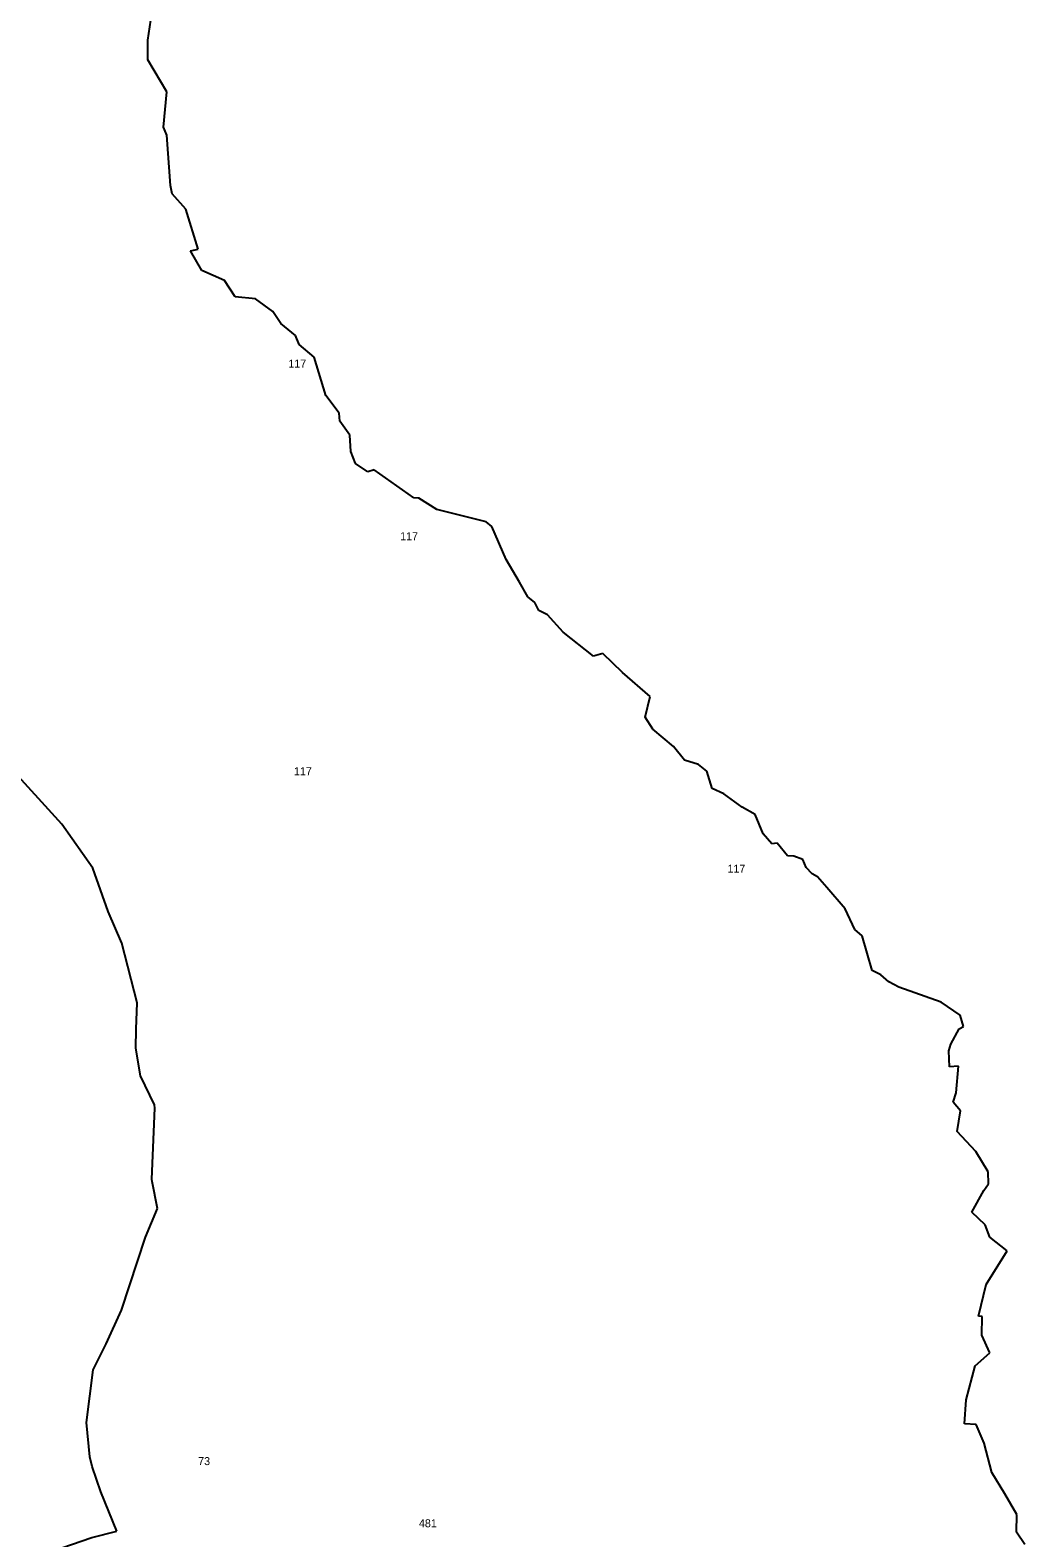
# Model space of a CAD drawing. Extents: x -782977 to -778030, y -975420 to -964838.
# Drawn here: x -780704 to -779844, y -972772 to -971468 of the extents above; entities that cross this region are included whole.
import ezdxf

# ---------------------------------------------------------------- set-up
doc = ezdxf.new("R2010")
doc.units = 0
doc.layers.add('Vrstva 13', color=7, linetype='Continuous')
doc.layers.add('Vrstva 24', color=7, linetype='Continuous')

msp = doc.modelspace()

# ---------------------------------------------------------------- linework, layer by layer
at = {"layer": 'Vrstva 13'}
for p, q in [((-780602.17, -971477.03), (-780599.62, -971459.93)), ((-780602.06, -971494.12), (-780602.17, -971477.03)), ((-780585.78, -971521.81), (-780602.06, -971494.12)), ((-780588.63, -971552.35), (-780585.78, -971521.81)), ((-780585.58, -971559.27), (-780588.63, -971552.35)), ((-780582.42, -971602.63), (-780585.58, -971559.27)), ((-780581.07, -971610.08), (-780582.42, -971602.63)), ((-780569.27, -971623.06), (-780581.07, -971610.08)), ((-780558.65, -971657.66), (-780569.27, -971623.06)), ((-780565.16, -971659.24), (-780558.65, -971657.66)), ((-780555.34, -971676.3), (-780565.16, -971659.24)), ((-780535.9, -971684.96), (-780555.34, -971676.3)), ((-780526.54, -971698.9), (-780535.9, -971684.96)), ((-780509.09, -971700.78), (-780526.54, -971698.9)), ((-780494.08, -971711.62), (-780509.09, -971700.78)), ((-780487.06, -971721.9), (-780494.08, -971711.62)), ((-780474.49, -971732.43), (-780487.06, -971721.9)), ((-780471.19, -971740.17), (-780474.49, -971732.43)), ((-780458.35, -971750.99), (-780471.19, -971740.17)), ((-780448.3, -971784.25), (-780458.35, -971750.99)), ((-780436.7, -971799.47), (-780448.3, -971784.25)), ((-780436.03, -971806.29), (-780436.7, -971799.47)), ((-780427.59, -971818.5), (-780436.03, -971806.29)), ((-780426.48, -971832.65), (-780427.59, -971818.5)), ((-780422.51, -971843.09), (-780426.48, -971832.65)), ((-780411.85, -971850.24), (-780422.51, -971843.09)), ((-780406.46, -971848.61), (-780411.85, -971850.24)), ((-780372.25, -971872.55), (-780406.46, -971848.61)), ((-780367.72, -971872.86), (-780372.25, -971872.55)), ((-780352.28, -971882.86), (-780367.72, -971872.86)), ((-780309.57, -971893.32), (-780352.28, -971882.86)), ((-780304.61, -971897.57), (-780309.57, -971893.32)), ((-780292.4, -971925.87), (-780304.61, -971897.57)), ((-780280.74, -971945.5), (-780292.4, -971925.87)), ((-780273.56, -971958.17), (-780280.74, -971945.5)), ((-780267.55, -971963.19), (-780273.56, -971958.17)), ((-780264.01, -971970.09), (-780267.55, -971963.19)), ((-780256.62, -971973.74), (-780264.01, -971970.09)), ((-780242.98, -971988.81), (-780256.62, -971973.74)), ((-780216.85, -972009.55), (-780242.98, -971988.81)), ((-780208.66, -972007.29), (-780216.85, -972009.55)), ((-780191.71, -972023.77), (-780208.66, -972007.29)), ((-780167.8, -972044.23), (-780191.71, -972023.77)), ((-780172.08, -972062.14), (-780167.8, -972044.23)), ((-780165.57, -972072.53), (-780172.08, -972062.14)), ((-780147.66, -972087.59), (-780165.57, -972072.53)), ((-780138.2, -972099.29), (-780147.66, -972087.59)), ((-780125.99, -972103.16), (-780138.2, -972099.29)), ((-780676.27, -972154.73), (-780722.73, -972103.79)), ((-780118.95, -972108.98), (-780125.99, -972103.16)), ((-780114.32, -972123.89), (-780118.95, -972108.98)), ((-780104.15, -972128.57), (-780114.32, -972123.89)), ((-780088.43, -972139.92), (-780104.15, -972128.57)), ((-780077.04, -972146.29), (-780088.43, -972139.92)), ((-780070.27, -972162.98), (-780077.04, -972146.29)), ((-780649.54, -972192.64), (-780676.27, -972154.73)), ((-780062.68, -972171.84), (-780070.27, -972162.98)), ((-780058, -972171.16), (-780062.68, -972171.84)), ((-780049.08, -972181.98), (-780058, -972171.16)), ((-780043.79, -972182.23), (-780049.08, -972181.98)), ((-780035.8, -972185.34), (-780043.79, -972182.23)), ((-780033.16, -972192.11), (-780035.8, -972185.34)), ((-780636.22, -972230.05), (-780649.54, -972192.64)), ((-780027.82, -972197.7), (-780033.16, -972192.11)), ((-780023.34, -972200.35), (-780027.82, -972197.7)), ((-780015.25, -972209.36), (-780023.34, -972200.35)), ((-779999.23, -972227.93), (-780015.25, -972209.36)), ((-779990.89, -972245.68), (-779999.23, -972227.93)), ((-780624.55, -972257.62), (-780636.22, -972230.05)), ((-779984.63, -972251.28), (-779990.89, -972245.68)), ((-779975.88, -972281.15), (-779984.63, -972251.28)), ((-780611.35, -972309.17), (-780624.55, -972257.62)), ((-779968.46, -972284.96), (-779975.88, -972281.15)), ((-779961.44, -972290.87), (-779968.46, -972284.96)), ((-779953.05, -972295.66), (-779961.44, -972290.87)), ((-779916.19, -972308.66), (-779953.05, -972295.66)), ((-780612.19, -972331.79), (-780611.35, -972309.17)), ((-779899.82, -972319.79), (-779916.19, -972308.66)), ((-779897.06, -972329.49), (-779899.82, -972319.79)), ((-780612.59, -972348.4), (-780612.19, -972331.79)), ((-779907.84, -972344.86), (-779900.9, -972331.58)), ((-779900.9, -972331.58), (-779897.06, -972329.49)), ((-779909.68, -972350.54), (-779907.84, -972344.86)), ((-780608.28, -972372.09), (-780612.59, -972348.4)), ((-779909.22, -972364.53), (-779909.68, -972350.54)), ((-780596.18, -972397.16), (-780608.28, -972372.09)), ((-779901.34, -972363.97), (-779909.22, -972364.53)), ((-779903.22, -972386.77), (-779901.34, -972363.97)), ((-780595.98, -972400.16), (-780596.18, -972397.16)), ((-779906.02, -972394.91), (-779903.22, -972386.77)), ((-779899.58, -972402.52), (-779906.02, -972394.91)), ((-780598.5, -972461.41), (-780595.98, -972400.16)), ((-779902.63, -972420.23), (-779899.58, -972402.52)), ((-779886.48, -972437.55), (-779902.63, -972420.23)), ((-779875.6, -972455.11), (-779886.48, -972437.55)), ((-780598.22, -972463.62), (-780598.5, -972461.41)), ((-780593.67, -972487.01), (-780598.22, -972463.62)), ((-779875.5, -972465.49), (-779875.6, -972455.11)), ((-779889.94, -972490.11), (-779879.51, -972471.19)), ((-779879.51, -972471.19), (-779875.5, -972465.49)), ((-780604.05, -972511.61), (-780593.67, -972487.01)), ((-779878.24, -972501.06), (-779889.94, -972490.11)), ((-779874.33, -972511.69), (-779878.24, -972501.06)), ((-780624.8, -972574.84), (-780604.05, -972511.61)), ((-779859.15, -972523.48), (-779874.33, -972511.69)), ((-779877.33, -972552.56), (-779859.15, -972523.48)), ((-779884.16, -972580.05), (-779877.33, -972552.56)), ((-780638.04, -972603.74), (-780624.8, -972574.84)), ((-779880.78, -972580.35), (-779884.16, -972580.05)), ((-779881.16, -972596.47), (-779880.78, -972580.35)), ((-780649.37, -972626.34), (-780639.72, -972607.18)), ((-780639.72, -972607.18), (-780638.04, -972603.74)), ((-779874.15, -972611.73), (-779881.16, -972596.47)), ((-779886.95, -972622.98), (-779874.15, -972611.73)), ((-780655.03, -972671.69), (-780649.37, -972626.34)), ((-779894.64, -972652.34), (-779886.95, -972622.98)), ((-779896.17, -972672.84), (-779894.64, -972652.34)), ((-780652.32, -972701.57), (-780655.03, -972671.69)), ((-779885.95, -972673.51), (-779896.17, -972672.84)), ((-779879.08, -972689.63), (-779885.95, -972673.51)), ((-779872.62, -972715.02), (-779879.08, -972689.63)), ((-780650.17, -972709.76), (-780652.32, -972701.57)), ((-780642.66, -972731.8), (-780650.17, -972709.76)), ((-779861.23, -972733.45), (-779872.62, -972715.02)), ((-780628.85, -972765.64), (-780642.66, -972731.8)), ((-779850.86, -972751.2), (-779861.23, -972733.45)), ((-779851.17, -972766.57), (-779850.86, -972751.2)), ((-780684.87, -972783.05), (-780650.48, -972771.15)), ((-780650.48, -972771.15), (-780628.85, -972765.64)), ((-779843.99, -972777.35), (-779851.17, -972766.57))]:
    msp.add_line(p, q, dxfattribs=at)

# ---------------------------------------------------------------- texts
at = {"layer": 'Vrstva 24'}
for s, p in [('117', (-780480.585, -971760.142)), ('117', (-780383.965, -971909.312)), ('117', (-780475.715, -972112.382)), ('117', (-780101.035, -972196.632)), ('73', (-780558.563, -972708.642)), ('481', (-780367.738, -972762.372))]:
    msp.add_text(s, height=6.912, dxfattribs=at).set_placement(p)

doc.saveas('drawing.dxf')
